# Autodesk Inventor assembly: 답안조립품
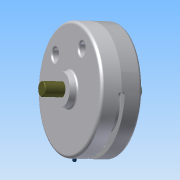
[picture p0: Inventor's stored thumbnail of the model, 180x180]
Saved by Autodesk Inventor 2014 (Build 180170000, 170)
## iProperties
Created: 2015-06
Part Number: 답안조립품
Document SubType Name: Assembly
Designer: Administrator
Author: Administrator
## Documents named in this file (10)
- C:\Documents and Settings\Administrator\바탕 화면\450631V1004\답안조립품.iam
- C:\Documents and Settings\Administrator\바탕 화면\450631V1004\1-본체.ipt
- C:\Documents and Settings\Administrator\바탕 화면\450631V1004\베어링62_22.ipt
- C:\Documents and Settings\Administrator\바탕 화면\450631V1004\축.ipt
- C:\Documents and Settings\Administrator\바탕 화면\450631V1004\평행핀.ipt
- C:\Documents and Settings\Administrator\바탕 화면\450631V1004\슬라이더2.ipt
- C:\Documents and Settings\Administrator\바탕 화면\450631V1004\멈춤링.ipt
- C:\Documents and Settings\Administrator\바탕 화면\450631V1004\슬라이더.ipt
- C:\Documents and Settings\Administrator\바탕 화면\450631V1004\덮개.ipt
- C:\Documents and Settings\Administrator\바탕 화면\450631V1004\M10x35.ipt
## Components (8 placed, 5 different names)
1. 1-본체:1
2. KS B 2023 62/22 - 22 x 50 x 14:1
3. KS B 1336 22 x 1.2:1
4. KS B 1336 22 x 1.2:2
5. KS B 2023 62/22 - 22 x 50 x 14:2
6. KS B 1320 B B 5 x  20:1 — 각도:2
7. KS B 1003 - 미터 M 10 x 35:1
8. KS B 1003 - 미터 M 10 x 35:2
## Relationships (1: Angle 1)
- 각도:2 [Angle]: KS B 1320 B B 5 x  20:1
